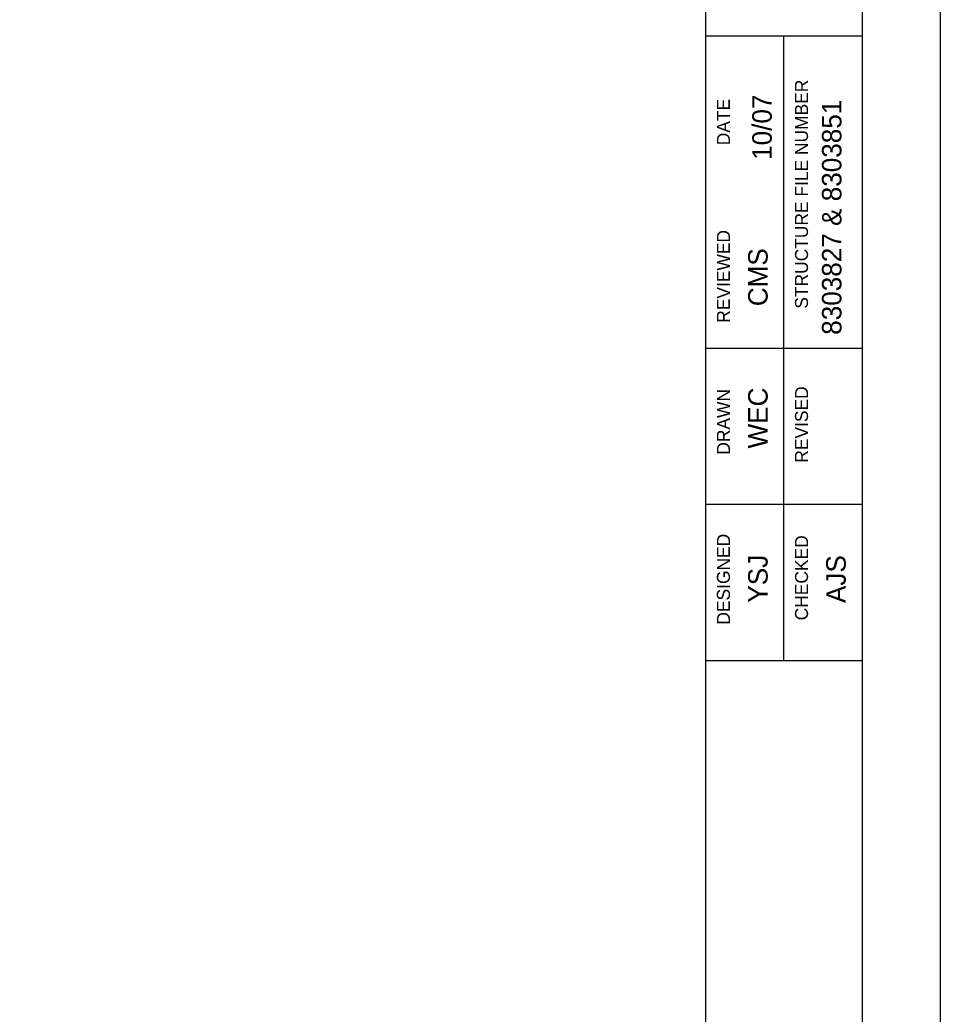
# Model space of a CAD drawing. Extents: x 1485751 to 1485785, y 230696.6 to 230718.6.
# Drawn here: x 1485779.14 to 1485785.03, y 230708.38 to 230714.74 of the extents above; entities that cross this region are included whole.
import ezdxf

# ---------------------------------------------------------------- set-up
doc = ezdxf.new("R2010")
doc.units = 0
for name, color, linetype in [('SH_Border', 7, 'Continuous'), ('SH_Cut_Line', 7, 'Continuous'), ('SH_Data', 7, 'Continuous')]:
    doc.layers.add(name, color=color, linetype=linetype)

msp = doc.modelspace()

# ---------------------------------------------------------------- linework, layer by layer
at = {"layer": 'SH_Border'}
for p, q in [((1485783.5329, 230697.1408), (1485783.5329, 230718.1408)), ((1485783.5329, 230697.1408), (1485783.5329, 230718.1408)), ((1485783.5329, 230697.1408), (1485783.5329, 230718.1408)), ((1485783.5329, 230714.6408), (1485784.5329, 230714.6408)), ((1485783.5329, 230714.6408), (1485784.5329, 230714.6408)), ((1485783.5329, 230714.6408), (1485784.5329, 230714.6408)), ((1485784.0329, 230710.6408), (1485784.0329, 230714.6408)), ((1485784.0329, 230710.6408), (1485784.0329, 230714.6408)), ((1485784.0329, 230710.6408), (1485784.0329, 230714.6408)), ((1485783.5329, 230712.6408), (1485784.5329, 230712.6408)), ((1485783.5329, 230712.6408), (1485784.5329, 230712.6408)), ((1485783.5329, 230712.6408), (1485784.5329, 230712.6408)), ((1485783.5329, 230711.6408), (1485784.5329, 230711.6408)), ((1485783.5329, 230711.6408), (1485784.5329, 230711.6408)), ((1485783.5329, 230711.6408), (1485784.5329, 230711.6408)), ((1485783.5329, 230710.6408), (1485784.5329, 230710.6408)), ((1485783.5329, 230710.6408), (1485784.5329, 230710.6408)), ((1485783.5329, 230710.6408), (1485784.5329, 230710.6408))]:
    msp.add_line(p, q, dxfattribs=at)
msp.add_lwpolyline([(1485753.0329, 230718.1408), (1485784.5329, 230718.1408), (1485784.5329, 230697.1408), (1485753.0329, 230697.1408)], close=True, dxfattribs=at)
at = {"layer": 'SH_Cut_Line'}
msp.add_lwpolyline([(1485751.0329, 230718.6408), (1485785.0329, 230718.6408), (1485785.0329, 230696.6408), (1485751.0329, 230696.6408)], close=True, dxfattribs=at)

# ---------------------------------------------------------------- texts
at = {"layer": 'SH_Data'}
for s, height, p in [('STRUCTURE FILE NUMBER', 0.0833, (1485784.187, 230712.8938)), ('10/07', 0.125, (1485783.9549, 230713.8469)), ('DATE', 0.0833, (1485783.687, 230713.9405)), ('8303827 & 8303851', 0.125, (1485784.4012, 230712.7264)), ('REVIEWED', 0.0833, (1485783.687, 230712.8035)), ('CMS', 0.125, (1485783.9287, 230712.9095)), ('DRAWN', 0.0833, (1485783.687, 230711.9585)), ('WEC', 0.125, (1485783.9287, 230711.9985)), ('REVISED', 0.0833, (1485784.187, 230711.9073)), ('DESIGNED', 0.0833, (1485783.687, 230710.87)), ('CHECKED', 0.0833, (1485784.187, 230710.8975)), ('YSJ', 0.125, (1485783.9287, 230711.0108)), ('AJS', 0.125, (1485784.4287, 230711.0083))]:
    msp.add_text(s, height=height, rotation=90, dxfattribs=at).set_placement(p)

doc.saveas('drawing.dxf')
